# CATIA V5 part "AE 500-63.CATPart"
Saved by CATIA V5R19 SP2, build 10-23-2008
Part number: AE 500-63
Bounding box of the stored display mesh (mm): x -22.494 to 22.494, y -22.494 to 22.494, z 0 to 177
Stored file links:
  C:\Users\Bora\Desktop\3D Katı model\AE serisi\AE 500\AE 500-63.CATPart
  C:\Program Files\Dassault Systemes\B19\intel_a\reffiles\standard\MetricThickPitch.txt
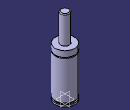
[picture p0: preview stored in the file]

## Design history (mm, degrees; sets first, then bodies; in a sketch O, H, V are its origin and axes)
Body1 (main body)
  Sketch1 on yz-plane, origin (0, 0, 0), H (0, 1, 0), V (0, 0, 1)
    point P1 (22.5, 97.5)
    point P8 (22.5, 99.5)
    point P9 (22.5, 99.5)
    point P10 (22.5, 97.5)
    point P11 (10, 175)
    point P13 (10, 175)
    line L1 (22.5, 97.5) -> (22.5, 8)
    line L2 (22.5, 4) -> (22.5, 0)
    line L3 (20, 8) -> (20, 4)
    line L4 (22.5, 113) -> (22.5, 99.5)
    arc A1 centre (22.5, 98.5) radius 1 from (22.5, 99.5) to (22.5, 97.5) ccw
    line L5 (10, 175) -> (10, 113)
    arc A2 centre (8, 175) radius 2 from (10, 175) to (8, 177) ccw
    line L6 (8, 177) -> (0, 177)
    point P15 (0, 177)
    line L7 (10, 113) -> (22.5, 113)
    line L8 (0, 0) -> (22.5, 0)
    line L9 (20, 8) -> (22.5, 8)
    line L10 (20, 4) -> (22.5, 4)
    coincidence: P15 V, P1 P10, P8 P9, P11 P13
    tangency: L6 A2
    horizontal: L7 H, L8 H, L9 H, L10 H
  Shaft1: profile Sketch1, axis Sketch1.V, angle 360
  Sketch2 on face of Shaft1 from Sketch1.L8, origin (0, 0, 0), H (1, 0, 0), V (0, -1, 0)
    point P1 (10, 0)
    distance P1 V = 10
  Hole1: placed by Sketch2, at (10, 0, 0) direction (0, 0, 1), diameter 6.647, depth 13, threaded "M8", thread diameter 8, thread depth 13, pitch 1.25
  CircPattern1: of Hole1, instances 2, angular step 180, axis from xy-plane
